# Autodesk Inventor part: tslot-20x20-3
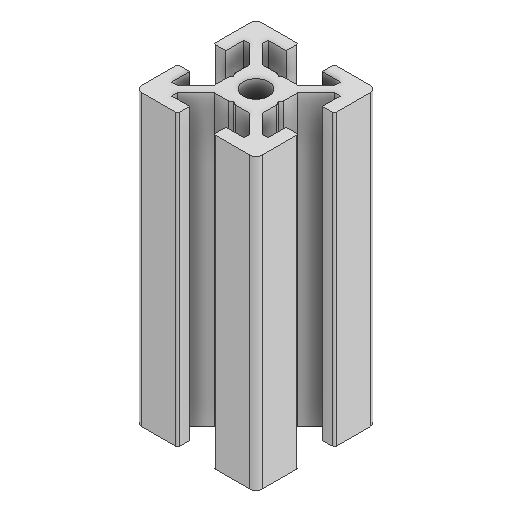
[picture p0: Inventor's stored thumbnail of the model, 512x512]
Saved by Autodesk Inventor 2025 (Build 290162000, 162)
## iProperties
Created: 2025-03
Part Number: tslot-20x20-3
Material: Generico
Document SubType Name: Modeling
Designer: Ryzen5700u
Density: 1 g/cm^3
Appearance: Default
Author: Ryzen5700u
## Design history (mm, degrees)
feature "Base1"
sketch "Schizzo1"
  geometry: L1 (3.761, -16)-(4.7, -16) reference; L2 (3.761, -16)-(0.7, -12.939) reference; L3 (0.7, -12.939)-(0.7, -10.52) reference; L4 (0.4, -10)-(0.7, -10.52) reference; L5 (0.4, -10)-(0.7, -9.48) reference; L6 (0.7, -7.061)-(0.7, -9.48) reference; L7 (3.761, -4)-(0.7, -7.061) reference; L8 (3.761, -4)-(4.7, -4) reference; L9 (4.7, -4)-(4.7, -7) reference; L10 (4.7, -7)-(6.4, -7) reference; L11 (6.7, -6.7)-(6.7, -1) reference; L12 (5.7, 0)-(0, 0) reference; L13 (-0.3, -2)-(-0.3, -0.3) reference; L14 (2.7, -2)-(-0.3, -2) reference; L15 (2.7, -2.939)-(2.7, -2) reference; L16 (2.7, -2.939)-(-0.361, -6) reference; L17 (-0.361, -6)-(-2.78, -6) reference; L18 (-3.3, -6.3)-(-2.78, -6) reference; L19 (-3.3, -6.3)-(-3.82, -6) reference; L20 (-6.239, -6)-(-3.82, -6) reference; L21 (-9.3, -2.939)-(-6.239, -6) reference; L22 (-9.3, -2.939)-(-9.3, -2) reference; L23 (-9.3, -2)-(-6.3, -2) reference; L24 (-6.3, -2)-(-6.3, -0.3) reference; L25 (-12.3, 0)-(-6.6, 0) reference; L26 (-13.3, -6.7)-(-13.3, -1) reference; L27 (-11.3, -7)-(-13, -7) reference; L28 (-11.3, -4)-(-11.3, -7) reference; L29 (-10.361, -4)-(-11.3, -4) reference; L30 (-10.361, -4)-(-7.3, -7.061) reference; L31 (-7.3, -7.061)-(-7.3, -9.48) reference; L32 (-7, -10)-(-7.3, -9.48) reference; L33 (-7, -10)-(-7.3, -10.52) reference; L34 (-7.3, -12.939)-(-7.3, -10.52) reference; L35 (-10.361, -16)-(-7.3, -12.939) reference; L36 (-10.361, -16)-(-11.3, -16) reference; L37 (-11.3, -16)-(-11.3, -13) reference; L38 (-11.3, -13)-(-13, -13) reference; L39 (-13.3, -13.3)-(-13.3, -19) reference; L40 (-12.3, -20)-(-6.6, -20) reference; L41 (-6.3, -18)-(-6.3, -19.7) reference; L42 (-9.3, -18)-(-6.3, -18) reference; L43 (-9.3, -17.061)-(-9.3, -18) reference; L44 (-9.3, -17.061)-(-6.239, -14) reference; L45 (-6.239, -14)-(-3.82, -14) reference; L46 (-3.3, -13.7)-(-3.82, -14) reference; L47 (-3.3, -13.7)-(-2.78, -14) reference; L48 (-0.361, -14)-(-2.78, -14) reference; L49 (2.7, -17.061)-(-0.361, -14) reference; L50 (2.7, -17.061)-(2.7, -18) reference; L51 (2.7, -18)-(-0.3, -18) reference; L52 (-0.3, -18)-(-0.3, -19.7) reference; L53 (5.7, -20)-(0, -20) reference; L54 (6.7, -13.3)-(6.7, -19) reference; L55 (4.7, -13)-(6.4, -13) reference; L56 (4.7, -16)-(4.7, -13) reference; C1 r 2.1 at (-3.3, -10) reference; A1 r 0.3 centre (6.4, -6.7) between (6.4, -7) and (6.7, -6.7) reference; A2 r 1 centre (5.7, -1) between (6.7, -1) and (5.7, 0) reference; A3 r 0.3 centre (0, -0.3) between (0, 0) and (-0.3, -0.3) reference; A4 r 0.3 centre (-6.6, -0.3) between (-6.3, -0.3) and (-6.6, 0) reference; A5 r 1 centre (-12.3, -1) between (-12.3, 0) and (-13.3, -1) reference; A6 r 0.3 centre (-13, -6.7) between (-13.3, -6.7) and (-13, -7) reference; A7 r 0.3 centre (-13, -13.3) between (-13, -13) and (-13.3, -13.3) reference; A8 r 1 centre (-12.3, -19) between (-13.3, -19) and (-12.3, -20) reference; A9 r 0.3 centre (-6.6, -19.7) between (-6.6, -20) and (-6.3, -19.7) reference; A10 r 0.3 centre (0, -19.7) between (-0.3, -19.7) and (0, -20) reference; A11 r 1 centre (5.7, -19) between (5.7, -20) and (6.7, -19) reference; A12 r 0.3 centre (6.4, -13.3) between (6.7, -13.3) and (6.4, -13) reference; 1 further point
extrude "Estrusione1" join sketch "Schizzo1" distance "d0" = 38; taper "d1" = 0 deg
node "Solido1"
node "Linea chiusa proiettata1"
